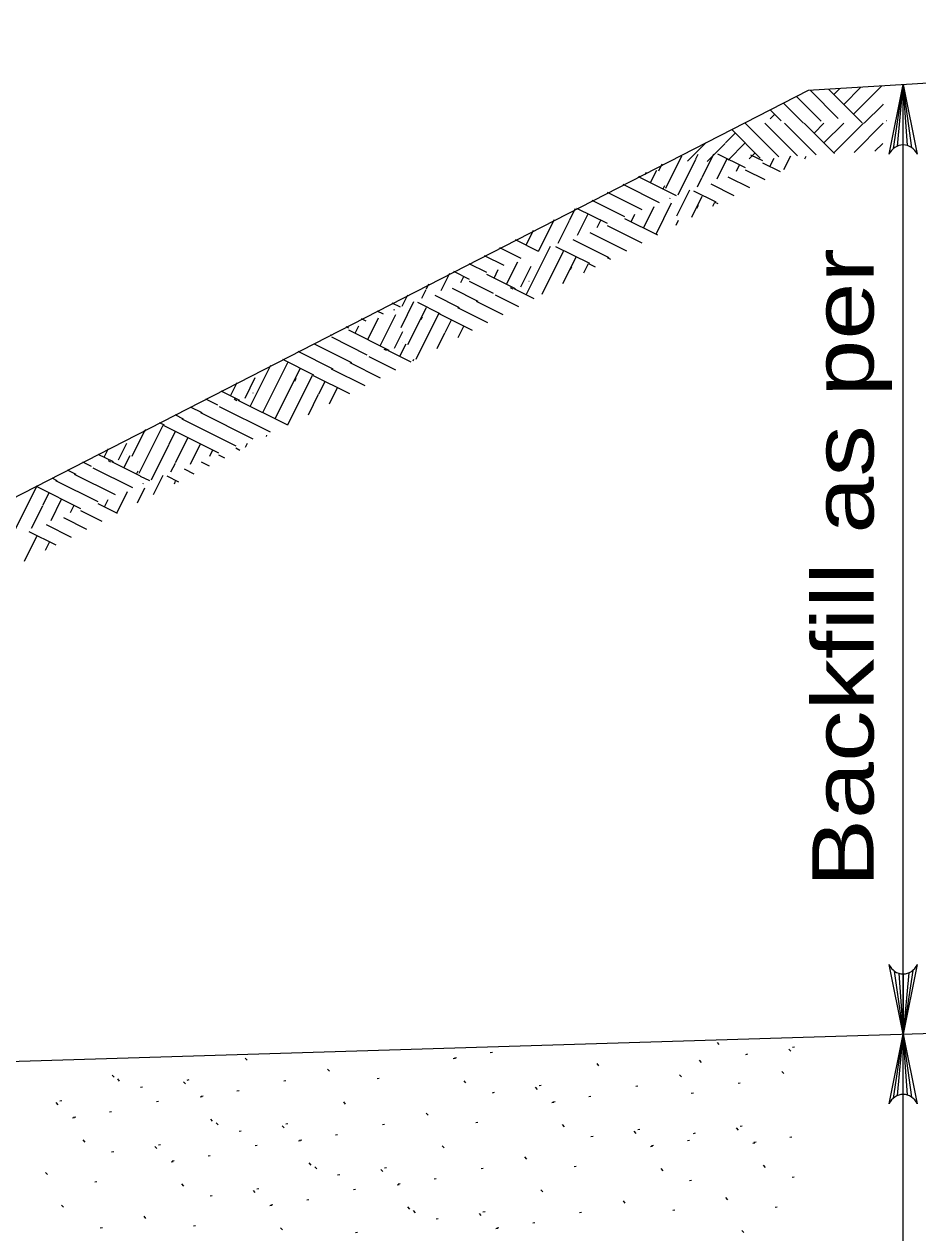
# Model space of a CAD drawing. Extents: x 1083.1 to 1117.1, y 697.4 to 741.4.
# Drawn here: x 1095.78 to 1098.05, y 704.879 to 707.948 of the extents above; entities that cross this region are included whole.
import ezdxf
from ezdxf.enums import TextEntityAlignment as Align

# ---------------------------------------------------------------- set-up
doc = ezdxf.new("R2010")
doc.units = 0
doc.header["$LTSCALE"] = 0.062
doc.layers.add('1', color=7, linetype='Continuous', lineweight=13)

msp = doc.modelspace()

# ---------------------------------------------------------------- linework, layer by layer
at = {"layer": '1', "lineweight": 25}
for p, q in [((1100.50475, 707.9485), (1097.77125, 707.78017)), ((1097.77125, 707.78017), (1092.11942, 704.88033)), ((1098.91383, 705.41058), (1093.14742, 705.23408)), ((1097.54533, 705.35725), (1097.5405, 705.36267)), ((1097.72692, 705.34058), (1097.72208, 705.34583)), ((1097.73125, 705.35025), (1097.73642, 705.35125)), ((1096.34575, 705.31758), (1096.34092, 705.32292)), ((1096.86983, 705.3215), (1096.875, 705.32233)), ((1096.8725, 705.32342), (1096.87775, 705.32425)), ((1096.96375, 705.33667), (1096.969, 705.33742)), ((1097.49992, 705.31183), (1097.495, 705.31717)), ((1097.61258, 705.33225), (1097.61775, 705.33325)), ((1096.00792, 705.274), (1096.00308, 705.27942)), ((1096.55533, 705.28917), (1096.5505, 705.29458)), ((1097.23967, 705.3035), (1097.23483, 705.30875)), ((1097.44925, 705.275), (1097.44442, 705.28042)), ((1097.70942, 705.28333), (1097.70467, 705.28875)), ((1096.02208, 705.2645), (1096.01725, 705.26983)), ((1096.07517, 705.249), (1096.08033, 705.24992)), ((1096.18958, 705.25725), (1096.18467, 705.26258)), ((1096.19383, 705.267), (1096.199, 705.268)), ((1096.43933, 705.26517), (1096.44458, 705.26617)), ((1096.67625, 705.27058), (1096.68142, 705.2715)), ((1096.90183, 705.25983), (1096.897, 705.26525)), ((1097.0835, 705.24317), (1097.07858, 705.2485)), ((1097.08775, 705.25283), (1097.09292, 705.25383)), ((1097.33325, 705.25108), (1097.3385, 705.252)), ((1097.59342, 705.25942), (1097.59867, 705.26033)), ((1096.22633, 705.22408), (1096.23158, 705.22492)), ((1096.229, 705.22608), (1096.23425, 705.22692)), ((1096.32025, 705.23925), (1096.3255, 705.24008)), ((1096.96908, 705.23483), (1096.97425, 705.23583)), ((1097.21417, 705.22517), (1097.21942, 705.226)), ((1097.47442, 705.2335), (1097.47958, 705.23433)), ((1095.86583, 705.20425), (1095.861, 705.20958)), ((1095.87017, 705.21392), (1095.87533, 705.21492)), ((1095.99658, 705.18617), (1096.00183, 705.187)), ((1096.11567, 705.21217), (1096.12092, 705.21308)), ((1096.59617, 705.20608), (1096.59133, 705.21142)), ((1097.12025, 705.21), (1097.1255, 705.21083)), ((1097.12292, 705.212), (1097.12817, 705.21283)), ((1095.90267, 705.171), (1095.90783, 705.17192)), ((1095.90533, 705.173), (1095.9105, 705.17383)), ((1096.25833, 705.1625), (1096.2535, 705.16792)), ((1096.2725, 705.153), (1096.26767, 705.15833)), ((1096.44433, 705.1555), (1096.4495, 705.15642)), ((1096.80575, 705.17767), (1096.801, 705.18308)), ((1096.92667, 705.15908), (1096.93183, 705.16)), ((1096.32558, 705.1375), (1096.33075, 705.13842)), ((1096.44, 705.14583), (1096.43517, 705.15108)), ((1096.57067, 705.12775), (1096.57592, 705.12858)), ((1096.68975, 705.15375), (1096.695, 705.15467)), ((1097.15225, 705.14833), (1097.14742, 705.15375)), ((1097.33392, 705.13167), (1097.329, 705.137)), ((1097.33817, 705.14142), (1097.34333, 705.14233)), ((1097.47975, 705.13167), (1097.48492, 705.13267)), ((1097.59408, 705.14), (1097.58925, 705.14533)), ((1097.59842, 705.14975), (1097.60358, 705.15067)), ((1095.93467, 705.10942), (1095.92983, 705.11483)), ((1096.11625, 705.09275), (1096.11142, 705.09808)), ((1096.12058, 705.10242), (1096.12575, 705.10342)), ((1096.36608, 705.10067), (1096.37133, 705.10158)), ((1096.47675, 705.11258), (1096.482, 705.11342)), ((1096.47942, 705.11458), (1096.48467, 705.11542)), ((1096.84667, 705.09458), (1096.84175, 705.09992)), ((1097.2195, 705.12333), (1097.22467, 705.12433)), ((1097.37067, 705.0985), (1097.37592, 705.09933)), ((1097.37333, 705.1005), (1097.37858, 705.10133)), ((1097.46458, 705.11367), (1097.46983, 705.1145)), ((1097.63083, 705.10683), (1097.63608, 705.10767)), ((1097.63358, 705.10883), (1097.63875, 705.10967)), ((1097.72483, 705.122), (1097.73, 705.12283)), ((1096.00192, 705.08442), (1096.00708, 705.08542)), ((1096.247, 705.07467), (1096.25225, 705.0755)), ((1097.05617, 705.06617), (1097.05142, 705.07158)), ((1096.15308, 705.05958), (1096.15825, 705.06042)), ((1096.15575, 705.0615), (1096.161, 705.06233)), ((1096.50875, 705.051), (1096.50392, 705.05642)), ((1096.52292, 705.0415), (1096.51808, 705.04683)), ((1096.69042, 705.03433), (1096.68558, 705.03958)), ((1096.69475, 705.044), (1096.69992, 705.045)), ((1096.94017, 705.04225), (1096.94542, 705.04317)), ((1097.17708, 705.04758), (1097.18225, 705.0485)), ((1097.40267, 705.03683), (1097.39783, 705.04225)), ((1097.66283, 705.04525), (1097.65808, 705.05067)), ((1095.83858, 705.02717), (1095.83375, 705.03258)), ((1095.9595, 705.00867), (1095.96467, 705.0095)), ((1096.18508, 704.99792), (1096.18025, 705.00333)), ((1096.576, 705.026), (1096.58125, 705.027)), ((1096.72983, 705.00308), (1096.73508, 705.00392)), ((1096.82108, 705.01625), (1096.82633, 705.01708)), ((1097.46992, 705.01192), (1097.47508, 705.01283)), ((1097.73017, 705.02025), (1097.73533, 705.02117)), ((1096.25233, 704.97292), (1096.2575, 704.97392)), ((1096.36675, 704.98125), (1096.36183, 704.98658)), ((1096.371, 704.99092), (1096.37617, 704.99192)), ((1096.6165, 704.98917), (1096.62175, 704.99008)), ((1096.72717, 705.00108), (1096.73242, 705.00192)), ((1097.09708, 704.98308), (1097.09217, 704.98842)), ((1095.87942, 704.94417), (1095.87458, 704.9495)), ((1096.4035, 704.94808), (1096.40875, 704.94892)), ((1096.40617, 704.95), (1096.41142, 704.95083)), ((1096.49742, 704.96317), (1096.50267, 704.964)), ((1096.75917, 704.9395), (1096.75433, 704.94492)), ((1097.30658, 704.95467), (1097.30183, 704.96008)), ((1097.56683, 704.963), (1097.562, 704.96842)), ((1097.68775, 704.9445), (1097.69283, 704.94533)), ((1096.089, 704.91567), (1096.08417, 704.92108)), ((1096.77333, 704.93), (1096.7685, 704.93533)), ((1096.8265, 704.9145), (1096.83167, 704.9155)), ((1096.94083, 704.92283), (1096.936, 704.92808)), ((1096.94517, 704.9325), (1096.95033, 704.9335)), ((1097.19058, 704.93075), (1097.19583, 704.93167)), ((1097.4275, 704.93617), (1097.43267, 704.937)), ((1095.973, 704.89175), (1095.97825, 704.89267)), ((1096.20992, 704.89717), (1096.21508, 704.898)), ((1096.4355, 704.88642), (1096.43067, 704.89183)), ((1096.62142, 704.87942), (1096.62658, 704.88042)), ((1096.97758, 704.88958), (1096.98283, 704.8905)), ((1096.98025, 704.89158), (1096.9855, 704.89242)), ((1097.07158, 704.90475), (1097.07675, 704.90558)), ((1097.60767, 704.87992), (1097.60283, 704.88525))]:
    msp.add_line(p, q, dxfattribs=at)
at = {"layer": '1'}
for p, q in [((1097.77592, 707.7805), (1097.8475, 707.70892)), ((1097.82308, 707.78333), (1097.90842, 707.698)), ((1097.8365, 707.77), (1097.85167, 707.78517)), ((1097.8615, 707.74492), (1097.905, 707.78842)), ((1097.8865, 707.71992), (1097.95825, 707.79167)), ((1097.98775, 707.63292), (1098.0125, 707.79508)), ((1097.99808, 707.63908), (1098.0125, 707.79508)), ((1098.0125, 707.64192), (1098.0125, 707.79508)), ((1098.02383, 707.64025), (1098.0125, 707.79508)), ((1098.03492, 707.63483), (1098.0125, 707.79508)), ((1098.0125, 702.899), (1098.0125, 707.79508)), ((1097.70825, 707.74792), (1097.75908, 707.69708)), ((1097.74142, 707.76492), (1097.80417, 707.70217)), ((1097.91367, 707.69692), (1097.96058, 707.74383)), ((1097.96158, 707.74483), (1097.963, 707.74625)), ((1097.67458, 707.70817), (1097.68625, 707.71992)), ((1097.67508, 707.731), (1097.70275, 707.70342)), ((1097.97042, 707.70367), (1097.97075, 707.70392)), ((1097.57708, 707.68092), (1097.64967, 707.60833)), ((1097.61117, 707.69692), (1097.69683, 707.61125)), ((1097.66117, 707.69692), (1097.744, 707.61408)), ((1097.71142, 707.69692), (1097.79125, 707.617)), ((1097.76142, 707.69692), (1097.83833, 707.61992)), ((1097.78642, 707.67183), (1097.81142, 707.69692)), ((1097.81142, 707.64675), (1097.86158, 707.69692)), ((1097.8365, 707.62175), (1097.91158, 707.69692)), ((1097.88767, 707.62292), (1097.96158, 707.69692)), ((1097.46483, 707.60058), (1097.51175, 707.64758)), ((1097.51425, 707.6), (1097.56008, 707.64583)), ((1097.56117, 707.64683), (1097.58617, 707.67183)), ((1097.56767, 707.60325), (1097.61125, 707.64675)), ((1097.941, 707.62625), (1097.96058, 707.64583)), ((1097.40933, 707.53208), (1097.45033, 707.61408)), ((1097.48625, 707.60683), (1097.49217, 707.61875)), ((1097.50217, 707.55933), (1097.532, 707.61925)), ((1097.54125, 707.619), (1097.611, 707.58425)), ((1097.621, 707.6065), (1097.63625, 707.62175)), ((1097.62508, 707.61675), (1097.65483, 707.60192)), ((1097.70983, 707.57925), (1097.72708, 707.614)), ((1097.76317, 707.60675), (1097.76625, 707.61292)), ((1097.39167, 707.57583), (1097.4005, 707.59342)), ((1097.44058, 707.51533), (1097.48558, 707.60567)), ((1097.53975, 707.55542), (1097.56542, 707.607)), ((1097.58933, 707.57542), (1097.59708, 707.59125)), ((1097.65508, 707.5965), (1097.69983, 707.57408)), ((1097.67408, 707.58692), (1097.68483, 707.6085)), ((1097.33933, 707.56183), (1097.412, 707.52558)), ((1097.34108, 707.56292), (1097.3435, 707.56175)), ((1097.35733, 707.56633), (1097.36067, 707.57292)), ((1097.371, 707.546), (1097.38675, 707.57767)), ((1097.378, 707.58042), (1097.37817, 707.58033)), ((1097.49025, 707.53542), (1097.5015, 707.55808)), ((1097.56742, 707.561), (1097.62183, 707.53392)), ((1097.61133, 707.57875), (1097.66083, 707.554)), ((1097.26092, 707.52167), (1097.34842, 707.47808)), ((1097.30008, 707.54183), (1097.39233, 707.49583)), ((1097.40267, 707.53025), (1097.40675, 707.5385)), ((1097.41217, 707.52517), (1097.43575, 707.51342)), ((1097.43775, 707.46175), (1097.47067, 707.5275)), ((1097.47983, 707.52558), (1097.53675, 707.49725)), ((1097.52367, 707.54333), (1097.58275, 707.51375)), ((1097.22183, 707.50167), (1097.30458, 707.46042)), ((1097.38475, 707.41508), (1097.42442, 707.49475)), ((1097.42008, 707.50558), (1097.421, 707.50742)), ((1097.47575, 707.45858), (1097.50233, 707.51183)), ((1097.16525, 707.45083), (1097.17983, 707.48)), ((1097.18283, 707.48158), (1097.26075, 707.44275)), ((1097.18567, 707.41233), (1097.21275, 707.46675)), ((1097.32142, 707.44667), (1097.33092, 707.46567)), ((1097.35308, 707.43083), (1097.38042, 707.48575)), ((1097.48867, 707.48125), (1097.49233, 707.48867)), ((1097.0865, 707.37233), (1097.12667, 707.45275)), ((1097.136, 707.39233), (1097.16458, 707.44958)), ((1097.23517, 707.43242), (1097.24442, 707.45092)), ((1097.26092, 707.43733), (1097.34908, 707.39333)), ((1097.30467, 707.45508), (1097.38808, 707.41342)), ((1097.43583, 707.43808), (1097.44225, 707.45075)), ((1097.02658, 707.40133), (1097.0855, 707.37192)), ((1097.0545, 707.38742), (1097.0735, 707.42542)), ((1097.17317, 707.40183), (1097.26458, 707.35625)), ((1097.217, 707.41958), (1097.31, 707.37317)), ((1096.9875, 707.38125), (1097.04175, 707.35417)), ((1097.055, 707.26108), (1097.11642, 707.38442)), ((1097.09525, 707.2625), (1097.15008, 707.37233)), ((1097.1295, 707.38417), (1097.21567, 707.34117)), ((1096.90933, 707.34108), (1096.954, 707.31875)), ((1096.94842, 707.36108), (1096.99783, 707.3365)), ((1097.00492, 707.288), (1097.03358, 707.34533)), ((1097.14842, 707.28992), (1097.18183, 707.35675)), ((1097.20167, 707.31733), (1097.21317, 707.34042)), ((1097.21317, 707.34042), (1097.23, 707.332)), ((1097.26058, 707.35625), (1097.269, 707.35208)), ((1096.83892, 707.27225), (1096.86075, 707.31608)), ((1096.87025, 707.321), (1096.91017, 707.30108)), ((1096.8885, 707.29233), (1096.89633, 707.30808)), ((1096.95425, 707.31333), (1097.02708, 707.277)), ((1096.97333, 707.30375), (1096.98408, 707.32542)), ((1097.0415, 707.28183), (1097.06767, 707.33417)), ((1097.16767, 707.32517), (1097.17117, 707.33217)), ((1096.78942, 707.25225), (1096.80075, 707.27492)), ((1096.80133, 707.27625), (1096.80758, 707.28875)), ((1096.86658, 707.27783), (1096.932, 707.24525)), ((1096.9105, 707.29567), (1096.97142, 707.26517)), ((1097.01408, 707.27975), (1097.021, 707.27633)), ((1097.02333, 707.27683), (1097.074, 707.25158)), ((1097.06167, 707.29567), (1097.06217, 707.29542)), ((1096.737, 707.17858), (1096.76983, 707.24433)), ((1096.73975, 707.23225), (1096.75433, 707.26142)), ((1096.82283, 707.26017), (1096.88442, 707.22933)), ((1096.92825, 707.24508), (1096.99592, 707.21133)), ((1096.97583, 707.261), (1097.035, 707.2315)), ((1096.67525, 707.22075), (1096.6915, 707.21275)), ((1096.714, 707.24067), (1096.73492, 707.23025)), ((1096.71925, 707.22242), (1096.72017, 707.22433)), ((1096.75467, 707.13483), (1096.8015, 707.22867)), ((1096.77575, 707.09792), (1096.83333, 707.21333)), ((1096.77908, 707.24242), (1096.83592, 707.21408)), ((1096.83333, 707.21333), (1096.91792, 707.17117)), ((1096.88083, 707.22917), (1096.95692, 707.19125)), ((1096.62058, 707.1635), (1096.63008, 707.1825)), ((1096.63608, 707.20067), (1096.64758, 707.195)), ((1096.65225, 707.14775), (1096.67967, 707.20258)), ((1096.68392, 707.13192), (1096.72367, 707.21158)), ((1096.78783, 707.19808), (1096.79158, 707.2055)), ((1096.84925, 707.16583), (1096.865, 707.1975)), ((1096.558, 707.1605), (1096.56, 707.15958)), ((1096.56008, 707.15425), (1096.65042, 707.10908)), ((1096.59708, 707.18058), (1096.60375, 707.17725)), ((1096.60383, 707.17192), (1096.70642, 707.12075)), ((1096.72033, 707.12533), (1096.74142, 707.16767)), ((1096.82892, 707.12525), (1096.84858, 707.16467)), ((1096.88233, 707.15283), (1096.89675, 707.18175)), ((1096.51617, 707.13642), (1096.61133, 707.089)), ((1096.69342, 707.1235), (1096.7, 707.12025)), ((1096.70225, 707.12083), (1096.76225, 707.09092)), ((1096.73392, 707.105), (1096.74975, 707.13667)), ((1096.741, 707.13942), (1096.74108, 707.13933)), ((1096.4355, 707.09758), (1096.51492, 707.05808)), ((1096.4745, 707.11767), (1096.56383, 707.07308)), ((1096.65483, 707.10492), (1096.72325, 707.07083)), ((1096.76792, 707.09383), (1096.76975, 707.0975)), ((1096.35417, 706.97792), (1096.40633, 707.08258)), ((1096.38583, 706.96217), (1096.44925, 707.08917)), ((1096.4175, 706.94633), (1096.481, 707.07367)), ((1096.55983, 707.07308), (1096.64517, 707.03058)), ((1096.60725, 707.089), (1096.68417, 707.05067)), ((1096.30417, 707.00483), (1096.32108, 707.03875)), ((1096.34067, 706.99867), (1096.36683, 707.05108)), ((1096.4495, 706.93133), (1096.51233, 707.05725)), ((1096.46683, 707.042), (1096.47033, 707.04908)), ((1096.51233, 707.05725), (1096.60617, 707.0105)), ((1096.52825, 707.00983), (1096.544, 707.04142)), ((1096.27925, 707.01733), (1096.32625, 706.99383)), ((1096.36083, 707.0125), (1096.36133, 707.01225)), ((1096.50167, 706.95667), (1096.52758, 707.00858)), ((1096.555, 706.98417), (1096.57575, 707.02567)), ((1096.20108, 706.97708), (1096.23117, 706.96208)), ((1096.24017, 706.99725), (1096.27067, 706.982)), ((1096.27508, 706.97783), (1096.40467, 706.91317)), ((1096.31325, 706.99667), (1096.32017, 706.99317)), ((1096.3225, 706.99375), (1096.4485, 706.93092)), ((1096.123, 706.937), (1096.13508, 706.931)), ((1096.162, 706.957), (1096.18367, 706.94625)), ((1096.18, 706.946), (1096.317, 706.87775)), ((1096.22742, 706.96192), (1096.36083, 706.8955)), ((1096.05383, 706.85167), (1096.08725, 706.91867)), ((1096.0715, 706.80792), (1096.13258, 706.93017)), ((1096.08708, 706.91492), (1096.08942, 706.91975)), ((1096.13258, 706.93017), (1096.27317, 706.86008)), ((1096.14842, 706.88275), (1096.16425, 706.91442)), ((1096.0195, 706.84225), (1096.04058, 706.8845)), ((1096.10275, 706.79117), (1096.14775, 706.8815)), ((1096.16433, 706.83517), (1096.19592, 706.89858)), ((1096.20192, 706.83125), (1096.22758, 706.88283)), ((1096.34208, 706.87433), (1096.347, 706.88442)), ((1096.39525, 706.90175), (1096.3965, 706.90433)), ((1095.967, 706.85683), (1096.00558, 706.83758)), ((1095.98317, 706.84883), (1095.99408, 706.87075)), ((1096.03317, 706.82183), (1096.04892, 706.8535)), ((1096.04017, 706.85625), (1096.04033, 706.85617)), ((1096.2515, 706.85133), (1096.25925, 706.86708)), ((1096.27342, 706.85458), (1096.28883, 706.84692)), ((1096.31725, 706.87233), (1096.32783, 706.867)), ((1095.88883, 706.81667), (1095.91058, 706.80583)), ((1095.92792, 706.83675), (1095.94958, 706.826)), ((1095.954, 706.82175), (1096.0545, 706.77167)), ((1095.99267, 706.84042), (1095.99917, 706.83708)), ((1096.0015, 706.83767), (1096.07417, 706.80142)), ((1096.06483, 706.80608), (1096.06892, 706.81433)), ((1096.15242, 706.81125), (1096.16367, 706.83392)), ((1096.18575, 706.81917), (1096.21075, 706.80667)), ((1096.22958, 706.83683), (1096.24975, 706.82683)), ((1095.84975, 706.79658), (1095.863, 706.79)), ((1095.859, 706.79), (1095.96675, 706.73625)), ((1095.90642, 706.80583), (1096.0105, 706.75392)), ((1096.07433, 706.801), (1096.09792, 706.78925)), ((1096.08225, 706.78142), (1096.08317, 706.78325)), ((1096.10808, 706.75383), (1096.13283, 706.80333)), ((1096.142, 706.80142), (1096.17175, 706.78658)), ((1096.16125, 706.78125), (1096.1645, 706.78767)), ((1095.74867, 706.64817), (1095.8115, 706.77408)), ((1095.81075, 706.77658), (1095.81408, 706.77492)), ((1095.8115, 706.77408), (1095.92292, 706.71858)), ((1095.82742, 706.72667), (1095.84317, 706.75833)), ((1096.01525, 706.70667), (1096.04258, 706.76158)), ((1096.06792, 706.73308), (1096.08658, 706.77058)), ((1095.79817, 706.66817), (1095.82675, 706.72542)), ((1095.84783, 706.68825), (1095.87492, 706.74258)), ((1095.89733, 706.70825), (1095.90658, 706.72675)), ((1095.96683, 706.73092), (1096.016, 706.70633)), ((1095.98358, 706.7225), (1095.99308, 706.7415)), ((1095.87917, 706.69542), (1095.93792, 706.66608)), ((1095.92308, 706.71317), (1095.977, 706.68625)), ((1095.83533, 706.67767), (1095.89892, 706.646)), ((1095.78075, 706.58508), (1095.81225, 706.64817)), ((1095.79167, 706.66), (1095.86, 706.62592)), ((1095.83392, 706.6125), (1095.844, 706.63258)), ((1097.99008, 705.54375), (1098.0125, 705.3835)), ((1098.00117, 705.53833), (1098.0125, 705.3835)), ((1098.03733, 705.54558), (1098.0125, 705.3835)), ((1098.02692, 705.5395), (1098.0125, 705.3835)), ((1098.0125, 705.53667), (1098.0125, 705.3835)), ((1097.98775, 705.22133), (1098.0125, 705.3835)), ((1097.99808, 705.2275), (1098.0125, 705.3835)), ((1098.0125, 705.23033), (1098.0125, 705.3835)), ((1098.02383, 705.22867), (1098.0125, 705.3835)), ((1098.03492, 705.22325), (1098.0125, 705.3835))]:
    msp.add_line(p, q, dxfattribs=at)
for points in [[(1097.97708, 707.61808), (1098.0125, 707.79508), (1098.04792, 707.61808)], [(1097.529, 707.486), (1097.53417, 707.49642), (1097.54183, 707.49267)], [(1098.04792, 705.5605), (1098.0125, 705.3835), (1097.97708, 705.5605)], [(1097.97708, 705.2065), (1098.0125, 705.3835), (1098.04792, 705.2065)]]:
    msp.add_lwpolyline(points, dxfattribs=at)
for centre, start, end in [((1098.01255, 707.60377), 22.08782, 157.91395), ((1098.01248, 705.57477), 202.08782, 337.91395), ((1098.01255, 705.19218), 22.08782, 157.91395)]:
    msp.add_arc(centre, 0.0382, start, end, dxfattribs=at)

# ---------------------------------------------------------------- texts
at = {"layer": '1', "width": 1.25}
msp.add_text('Backfill as per', height=0.156, rotation=90, dxfattribs=at).set_placement((1097.9375, 706.56767), align=Align.CENTER)

doc.saveas('drawing.dxf')
